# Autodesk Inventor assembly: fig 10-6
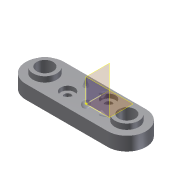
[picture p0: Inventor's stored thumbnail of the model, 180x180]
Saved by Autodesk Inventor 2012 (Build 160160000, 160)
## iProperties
Created: 2010-08
Part Number: fig 10-6
Document SubType Name: Assembly
Designer: CADSoft
Author: CADSoft
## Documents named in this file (2)
- C:\Users\CadCim\Documents\SAILESH\inventor-2011-fact-prt\c10-inv-2011-prt\c10_inv_2012_prt\fig 10-6.iam
- C:\Users\CadCim\Documents\SAILESH\inventor-2011-fact-prt\c10-inv-2011-prt\c10_inv_2012_prt\Part6.ipt
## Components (1 placed, 1 different names)
1. Part6:1
